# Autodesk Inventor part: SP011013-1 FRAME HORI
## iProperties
Created: 2013-01
Part Number: SP011013-1 FRAME HORI
Material: Aluminum-6061
Description: PROFILE 45X45 UL
Document SubType Name: Modeling
Designer: Administrator
Stock Number: 20.1063 PROFILE 45X45 UL
Density: 2.71 g/cm^3
Mass: 1775.23 g
Surface Area: 7771.49 cm^2
Volume: 655.068 cm^3
FINISH: CLEAR ANODIZED
Author: Administrator
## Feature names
1. Extrusion1
